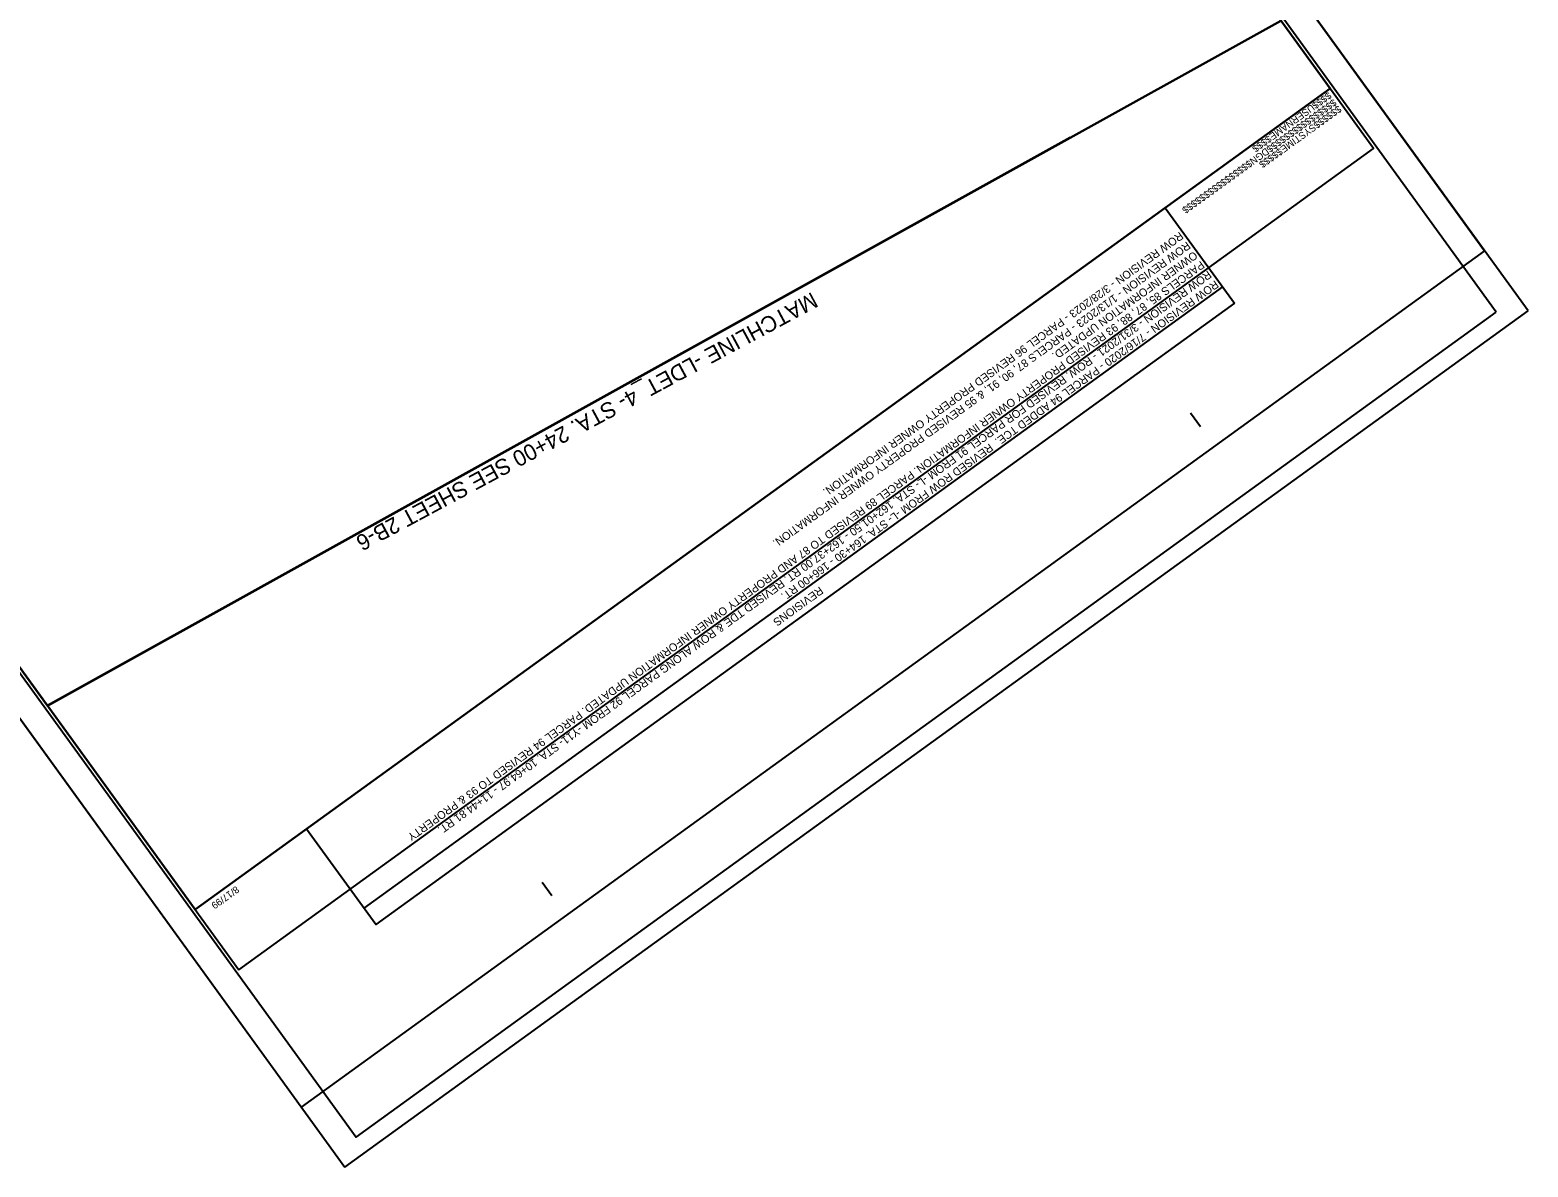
# Model space of a CAD drawing. Extents: x 474925 to 478950, y 494687 to 502905.
# Drawn here: x 475709 to 476832, y 500855 to 501707 of the extents above; entities that cross this region are included whole.
import ezdxf

# ---------------------------------------------------------------- set-up
doc = ezdxf.new("R2010")
doc.units = 0
for name, color, linetype in [('Matchline', 7, 'Continuous'), ('Matchline Text', 7, 'Continuous'), ('Sheet Block Revision CELL', 7, 'Continuous'), ('Sheet Cutting Line CELL', 7, 'Continuous'), ('Sheet Layout Plan Border', 7, 'Continuous'), ('Sheet Plan CELL', 7, 'Continuous'), ('Sheet Plan Layout CELL', 7, 'Continuous'), ('Sheet Plot Border Inside CELL', 7, 'Continuous'), ('Sheet Plot Border Outside CELL', 7, 'Continuous')]:
    doc.layers.add(name, color=color, linetype=linetype)

msp = doc.modelspace()

# ---------------------------------------------------------------- linework, layer by layer
at = {"layer": 'Matchline'}
msp.add_line((476488.5, 501626.6), (475722, 501200.7), dxfattribs=at)
at = {"layer": 'Sheet Block Revision CELL'}
msp.add_line((476602.7, 501514.7), (475959.2, 501048.7), dxfattribs=at)
msp.add_lwpolyline([(476611.6, 501502.5), (475968.1, 501036.5), (475916.2, 501108.1), (476559.7, 501574)], close=True, dxfattribs=at)
at = {"layer": 'Sheet Cutting Line CELL'}
for p, q in [((476831.7, 501496.8), (475844.4, 502860.4)), ((474957.5, 502218.2), (475944.8, 500854.6)), ((475944.8, 500854.6), (476831.7, 501496.8))]:
    msp.add_line(p, q, dxfattribs=at)
at = {"layer": 'Sheet Layout Plan Border'}
for points in [[(476646.4, 501714.4), (476110.2, 502454.9), (476091.7, 502441.6), (476003.5, 502563.5), (475989.4, 502553.3), (475869.1, 502719.5), (475838.1, 502697), (475782.5, 502773.7), (475678.6, 502698.5), (475653, 502679.9), (475264.4, 502398.5), (475136.1, 502305.7), (475211, 502202.4), (475104.2, 502125.1), (475196.5, 501997.6), (475162.7, 501973.1), (475722, 501200.7)], [(476646.5, 501714.2), (476022, 502576.7), (475989.4, 502553.3), (475869.2, 502719.3), (475838.2, 502696.9), (475782.7, 502773.5), (475678.8, 502698.3), (475653.1, 502679.7), (475264.5, 502398.4), (475136.3, 502305.6), (475211.1, 502202.2), (475104.3, 502124.9), (475196.6, 501997.5), (475162.8, 501973), (475722.1, 501200.5)]]:
    msp.add_lwpolyline(points, close=True, dxfattribs=at)
at = {"layer": 'Sheet Plan CELL'}
for p, q in [((476683.3, 501663.5), (476683.3, 501663.5)), ((476586.1, 501409.8), (476578.8, 501419.9)), ((476100.1, 501057.9), (476092.8, 501068)), ((475832.8, 501047.7), (475832.8, 501047.7))]:
    msp.add_line(p, q, dxfattribs=at)
for points in [[(474953, 502262.6), (475832.8, 501047.7), (476683.3, 501663.5), (475803.5, 502878.4)], [(476683.3, 501663.5), (475832.8, 501047.7), (475070.4, 502100.6), (475191.9, 502188.6), (475074.6, 502350.6), (475803.5, 502878.4)]]:
    msp.add_lwpolyline(points, close=True, dxfattribs=at)
at = {"layer": 'Sheet Plan Layout CELL'}
msp.add_lwpolyline([(475865.4, 501002.6), (476715.9, 501618.4), (475836.1, 502833.4), (475157, 502341.6), (475297.3, 502147.8), (475126, 502023.8)], close=True, dxfattribs=at)
at = {"layer": 'Sheet Plot Border Inside CELL'}
msp.add_lwpolyline([(476807.9, 501495.6), (475830.8, 502845), (474976.3, 502226.3), (475953.4, 500876.9)], close=True, dxfattribs=at)
at = {"layer": 'Sheet Plot Border Outside CELL'}
msp.add_lwpolyline([(475811.8, 502905.4), (476799.1, 501541.8), (475912.2, 500899.6), (474924.9, 502263.2)], close=True, dxfattribs=at)

# ---------------------------------------------------------------- texts
at = {"layer": 'Matchline Text'}
msp.add_text('MATCHLINE -LDET_4- STA. 24+00 SEE SHEET 2B-6', height=12, rotation=208.2628, dxfattribs=at).set_placement((476295, 501511.1))
at = {"layer": 'Sheet Block Revision CELL'}
for s, p in [('ROW REVISION - 3/28/2023 - PARCEL 96 REVISED PROPERTY OWNER INFORMATION. ', (476570.6, 501556.3)), ('ROW REVISION - 1/13/2023 - PARCELS 87, 90, 91, & 95 REVISED PROPERTY OWNER INFORMATION.', (476575.9, 501549)), ('PARCELS 85, 87, 88, 93 REVISED PROPERTY OWNER INFORMATION. PARCEL 89 REVISED TO 87 AND PROPERTY OWNER INFORMATION UPDATED. PARCEL 94 REVISED TO 93 & PROPERTY ', (476586.4, 501534.5)), ('OWNER INFORMATION UPDATED.', (476581.2, 501541.7)), ('ROW REVISION - 3/31/2021 - ROW. REVISED FOR PARCEL 91 FROM -L- STA. 162+01.50 - 162+37.00 RT. REVISED TDE & ROW ALONG PARCEL 92 FROM -Y11- STA. 10+64.97 - 11+44.81 RT.', (476591.7, 501527.2)), ('ROW REVISION - 7/16/2020 - PARCEL 94 ADDED TCE.  REVISED ROW FROM -L- STA. 164+30 - 166+00 RT.', (476597, 501519.9)), ('REVISIONS', (476300.7, 501290.3))]:
    msp.add_text(s, height=6, rotation=215.9074, dxfattribs=at).set_placement(p)
at = {"layer": 'Sheet Plan CELL'}
for s, p in [('$$$$$$$$$$$$$$$$DGN$$$$$$$$$$$$$$$$', (476685.8, 501655.9)), ('$$$$USERNAME$$$$', (476682, 501661.2)), ('$$$$$$SYSTIME$$$$$', (476689.4, 501651)), ('8/17/99', (475863.2, 501065.7))]:
    msp.add_text(s, height=5.25, rotation=215.9074, dxfattribs=at).set_placement(p)

doc.saveas('drawing.dxf')
